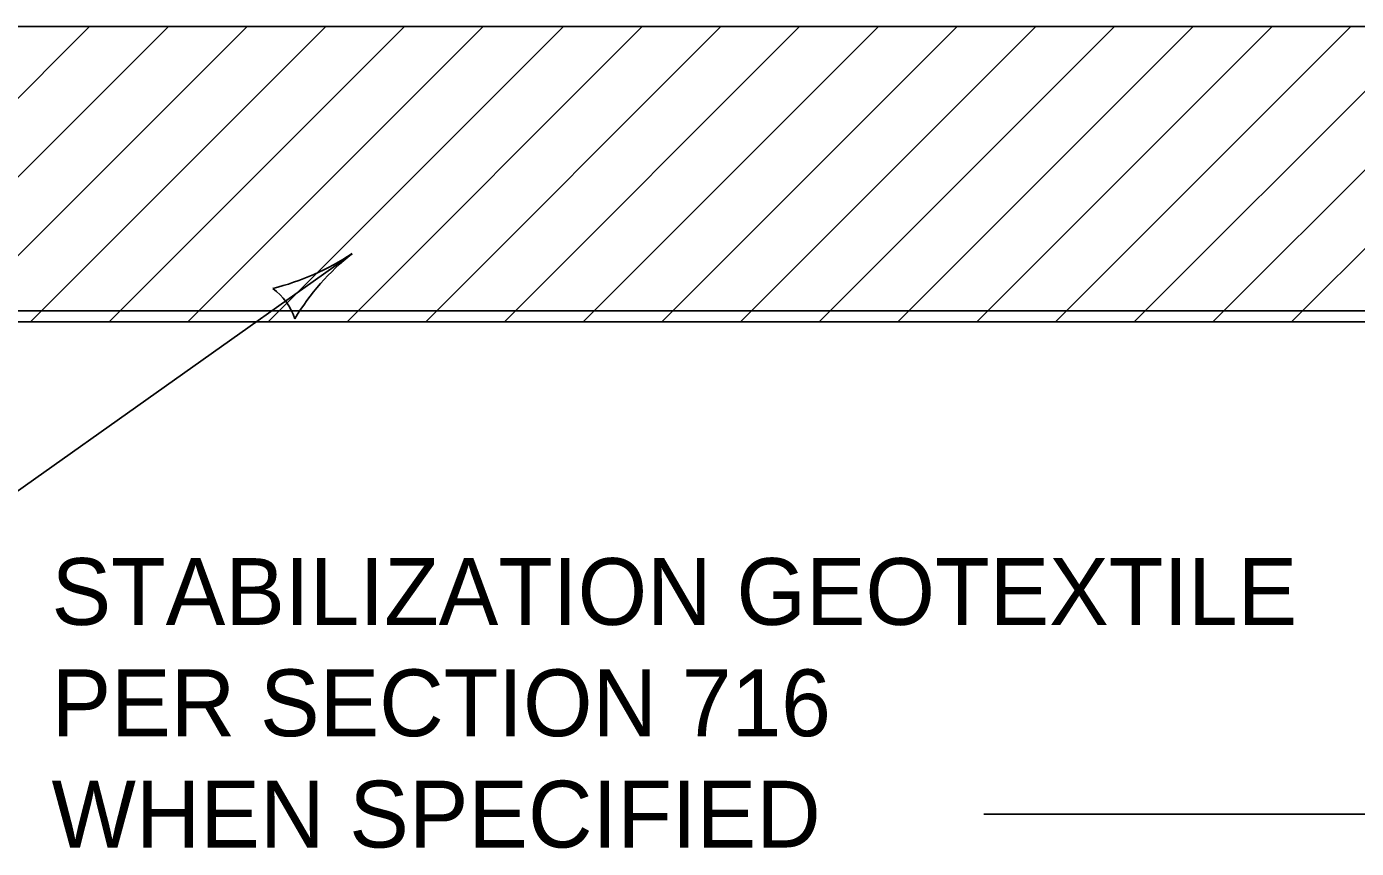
# Model space of a CAD drawing. Extents: x 49991.4 to 50021, y 49987.6 to 50011.4.
# Drawn here: x 50018.747 to 50019.942, y 50005.816 to 50006.555 of the extents above; entities that cross this region are included whole.
import ezdxf

# ---------------------------------------------------------------- set-up
doc = ezdxf.new("R2010")
doc.units = 0
for name, color, linetype in [('Level 1', 7, 'Continuous'), ('Level 2', 7, 'Continuous'), ('Level 3', 7, 'Continuous')]:
    doc.layers.add(name, color=color, linetype=linetype)

msp = doc.modelspace()

# ---------------------------------------------------------------- linework, layer by layer
at = {"layer": 'Level 1'}
for p, q in [((50017.1193, 50006.5545), (50020.4675, 50006.5545)), ((50018.5387, 50006.2893), (50018.8039, 50006.5545)), ((50018.6094, 50006.2893), (50018.8746, 50006.5545)), ((50018.6801, 50006.2893), (50018.9453, 50006.5545)), ((50018.7508, 50006.2893), (50019.016, 50006.5545)), ((50018.8215, 50006.2893), (50019.0867, 50006.5545)), ((50018.8922, 50006.2893), (50019.1574, 50006.5545)), ((50018.9644, 50006.2893), (50019.2296, 50006.5545)), ((50019.0351, 50006.2893), (50019.3003, 50006.5545)), ((50019.1058, 50006.2893), (50019.371, 50006.5545)), ((50019.1765, 50006.2893), (50019.4417, 50006.5545)), ((50019.2472, 50006.2893), (50019.5124, 50006.5545)), ((50019.3179, 50006.2893), (50019.5831, 50006.5545)), ((50019.3886, 50006.2893), (50019.6538, 50006.5545)), ((50019.4593, 50006.2893), (50019.7245, 50006.5545)), ((50019.53, 50006.2893), (50019.7952, 50006.5545)), ((50019.6008, 50006.2893), (50019.866, 50006.5545)), ((50019.6715, 50006.2893), (50019.9367, 50006.5545)), ((50019.7422, 50006.2893), (50020.0074, 50006.5545)), ((50019.8129, 50006.2893), (50020.0781, 50006.5545)), ((50019.8836, 50006.2893), (50020.1488, 50006.5545)), ((50017.1276, 50006.2993), (50020.4675, 50006.2993)), ((50017.1193, 50006.2893), (50020.4675, 50006.2893))]:
    msp.add_line(p, q, dxfattribs=at)
at = {"layer": 'Level 3'}
for p, q in [((50019.0397, 50006.3505), (50018.3298, 50005.847)), ((50019.607, 50005.847), (50020.0403, 50005.847))]:
    msp.add_line(p, q, dxfattribs=at)
for centre, radius, start, end in [((50018.9116, 50006.5452), 0.233, 284.0874, 303.3372), ((50019.1781, 50006.1766), 0.2223, 128.525, 148.7085), ((50018.9362, 50006.2748), 0.0548, 18.3034, 54.0257)]:
    msp.add_arc(centre, radius, start, end, dxfattribs=at)

# ---------------------------------------------------------------- texts
at = {"layer": 'Level 2'}
for s, p in [('STABILIZATION GEOTEXTILE ', (50018.7697, 50006.017)), ('PER SECTION 716', (50018.7697, 50005.917)), ('WHEN SPECIFIED', (50018.7697, 50005.817))]:
    msp.add_text(s, height=0.06, dxfattribs=at).set_placement(p)

doc.saveas('drawing.dxf')
